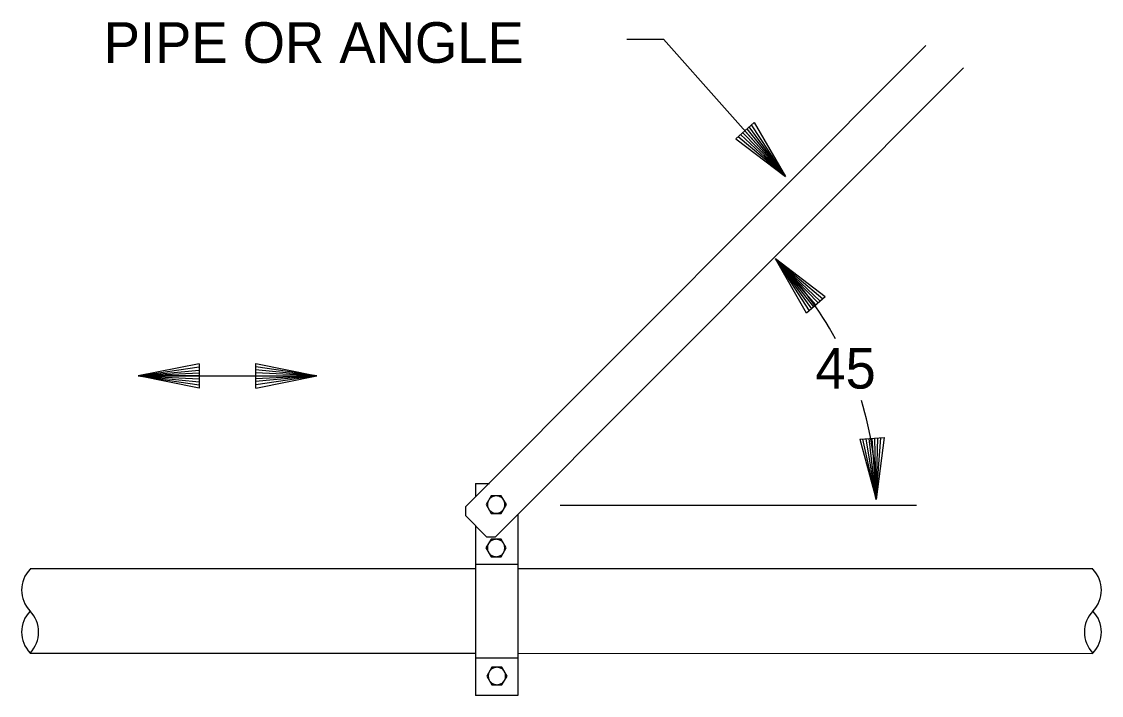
# Model space of a CAD drawing. Extents: x 10040.55 to 10045.84, y 10033.26 to 10035.76.
# Drawn here: x 10041.3056 to 10041.5711, y 10035.0779 to 10035.2436 of the extents above; entities that cross this region are included whole.
import ezdxf

# ---------------------------------------------------------------- set-up
doc = ezdxf.new("R2010")
doc.units = 0
doc.layers.add('Level 2', color=7, linetype='Continuous')

msp = doc.modelspace()

# ---------------------------------------------------------------- linework, layer by layer
at = {"layer": 'Level 2'}
for p, q in [((10041.414760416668, 10035.12428125), (10041.527947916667, 10035.237791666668)), ((10041.42215625, 10035.116947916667), (10041.537187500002, 10035.232312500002)), ((10041.481208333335, 10035.214812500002), (10041.485718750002, 10035.218802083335)), ((10041.483437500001, 10035.216802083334), (10041.493458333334, 10035.205552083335)), ((10041.493458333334, 10035.205552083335), (10041.484010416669, 10035.217291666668)), ((10041.493458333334, 10035.205552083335), (10041.484552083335, 10035.217791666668)), ((10041.493458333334, 10035.205552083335), (10041.485104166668, 10035.218270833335)), ((10041.485718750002, 10035.218802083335), (10041.493458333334, 10035.205552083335)), ((10041.481208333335, 10035.214812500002), (10041.493458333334, 10035.205552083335)), ((10041.493458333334, 10035.205552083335), (10041.48178125, 10035.215322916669)), ((10041.493458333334, 10035.205552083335), (10041.482395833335, 10035.215895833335)), ((10041.493458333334, 10035.205552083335), (10041.482916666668, 10035.216322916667)), ((10041.5009375, 10035.173968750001), (10041.490979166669, 10035.185270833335)), ((10041.498625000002, 10035.17196875), (10041.490979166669, 10035.185270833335)), ((10041.503166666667, 10035.175927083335), (10041.490979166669, 10035.185270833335)), ((10041.490979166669, 10035.185270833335), (10041.499812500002, 10035.172968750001)), ((10041.490979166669, 10035.185270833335), (10041.50196875, 10035.174854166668)), ((10041.490979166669, 10035.185270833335), (10041.499260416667, 10035.172510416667)), ((10041.490979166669, 10035.185270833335), (10041.500354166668, 10035.173468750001)), ((10041.490979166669, 10035.185270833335), (10041.501458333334, 10035.174437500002)), ((10041.490979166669, 10035.185270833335), (10041.502593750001, 10035.175427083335)), ((10041.503166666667, 10035.175927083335), (10041.498625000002, 10035.17196875)), ((10041.34928125, 10035.159500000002), (10041.334229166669, 10035.156500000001)), ((10041.334229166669, 10035.156500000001), (10041.34928125, 10035.158739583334)), ((10041.34928125, 10035.159500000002), (10041.349270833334, 10035.153479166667)), ((10041.363166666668, 10035.153500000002), (10041.363177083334, 10035.159520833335)), ((10041.378218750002, 10035.156500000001), (10041.363166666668, 10035.158708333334)), ((10041.363177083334, 10035.159520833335), (10041.378218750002, 10035.156500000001)), ((10041.334229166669, 10035.156500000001), (10041.349302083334, 10035.157895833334)), ((10041.334229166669, 10035.156500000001), (10041.34928125, 10035.15721875)), ((10041.349291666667, 10035.156520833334), (10041.334229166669, 10035.156500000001)), ((10041.334229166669, 10035.156500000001), (10041.378218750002, 10035.156500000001)), ((10041.349270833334, 10035.153479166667), (10041.334229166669, 10035.156500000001)), ((10041.334229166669, 10035.156500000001), (10041.349291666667, 10035.155020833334)), ((10041.334229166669, 10035.156500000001), (10041.34928125, 10035.154291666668)), ((10041.334229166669, 10035.156500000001), (10041.34928125, 10035.155760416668)), ((10041.378218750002, 10035.156500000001), (10041.363145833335, 10035.155104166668)), ((10041.378218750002, 10035.156500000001), (10041.363156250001, 10035.157979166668)), ((10041.363156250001, 10035.156479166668), (10041.378218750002, 10035.156500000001)), ((10041.378218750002, 10035.156500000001), (10041.363166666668, 10035.157239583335)), ((10041.363166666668, 10035.153500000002), (10041.378218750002, 10035.156500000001)), ((10041.378218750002, 10035.156500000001), (10041.363166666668, 10035.155781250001)), ((10041.378218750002, 10035.156500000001), (10041.363166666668, 10035.154260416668)), ((10041.511708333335, 10035.140895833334), (10041.517729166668, 10035.141322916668)), ((10041.511708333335, 10035.140895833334), (10041.515760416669, 10035.126093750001)), ((10041.515760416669, 10035.126093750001), (10041.512479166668, 10035.140958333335)), ((10041.515760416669, 10035.126093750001), (10041.513312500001, 10035.141031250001)), ((10041.515760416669, 10035.126093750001), (10041.513979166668, 10035.1410625)), ((10041.514687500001, 10035.141114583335), (10041.515760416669, 10035.126093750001)), ((10041.515760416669, 10035.126093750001), (10041.515437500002, 10035.141166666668)), ((10041.517729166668, 10035.141322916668), (10041.515760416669, 10035.126093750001)), ((10041.515760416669, 10035.126093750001), (10041.51690625, 10035.141260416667)), ((10041.515760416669, 10035.126093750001), (10041.516187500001, 10035.141229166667)), ((10041.41721875, 10035.130041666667), (10041.41721875, 10035.126750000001)), ((10041.41721875, 10035.130041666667), (10041.420656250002, 10035.130041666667)), ((10041.414760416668, 10035.124270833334), (10041.414760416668, 10035.122125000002)), ((10041.438000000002, 10035.124739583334), (10041.525697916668, 10035.124739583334)), ((10041.414760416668, 10035.122125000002), (10041.419958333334, 10035.116947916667)), ((10041.427635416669, 10035.122447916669), (10041.427635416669, 10035.07790625)), ((10041.41721875, 10035.119677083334), (10041.41721875, 10035.07790625)), ((10041.419958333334, 10035.116947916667), (10041.422166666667, 10035.116947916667)), ((10041.3076875, 10035.109093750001), (10041.41721875, 10035.109093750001)), ((10041.417229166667, 10035.110229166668), (10041.427666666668, 10035.110229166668)), ((10041.427635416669, 10035.109093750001), (10041.569041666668, 10035.109083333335)), ((10041.3076875, 10035.088260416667), (10041.41721875, 10035.088260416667)), ((10041.417229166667, 10035.087135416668), (10041.427666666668, 10035.087135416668)), ((10041.422322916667, 10035.087125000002), (10041.422322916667, 10035.087125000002)), ((10041.427635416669, 10035.088260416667), (10041.569041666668, 10035.08825)), ((10041.427635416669, 10035.07790625), (10041.41721875, 10035.07790625))]:
    msp.add_line(p, q, dxfattribs=at)
msp.add_lwpolyline([(10041.454468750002, 10035.239291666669), (10041.463468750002, 10035.239291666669), (10041.493458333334, 10035.205552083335)], dxfattribs=at)
for points in [[(10041.424812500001, 10035.124843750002), (10041.423562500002, 10035.127010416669), (10041.421062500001, 10035.127010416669), (10041.419812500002, 10035.124843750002), (10041.421062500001, 10035.122677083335), (10041.423562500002, 10035.122677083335)], [(10041.424458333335, 10035.124843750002), (10041.424447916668, 10035.124979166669), (10041.424437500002, 10035.125114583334), (10041.424416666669, 10035.125239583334), (10041.424385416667, 10035.125375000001), (10041.424354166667, 10035.125500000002), (10041.424302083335, 10035.125625), (10041.424250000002, 10035.125750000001), (10041.4241875, 10035.125875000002), (10041.424125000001, 10035.125989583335), (10041.424052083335, 10035.126104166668), (10041.423968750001, 10035.126208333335), (10041.423875, 10035.1263125), (10041.423781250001, 10035.126406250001), (10041.423677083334, 10035.126489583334), (10041.423572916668, 10035.126572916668), (10041.423458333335, 10035.126645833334), (10041.42334375, 10035.126718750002), (10041.423229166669, 10035.126781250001), (10041.423104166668, 10035.126833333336), (10041.422979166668, 10035.126875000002), (10041.42284375, 10035.126916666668), (10041.422718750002, 10035.126947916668), (10041.422583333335, 10035.12696875), (10041.422447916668, 10035.126979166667), (10041.4223125, 10035.126979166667), (10041.422177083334, 10035.126979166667), (10041.422041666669, 10035.12696875), (10041.421916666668, 10035.126947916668), (10041.421781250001, 10035.126916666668), (10041.42165625, 10035.126875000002), (10041.421531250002, 10035.126833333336), (10041.421406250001, 10035.126781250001), (10041.42128125, 10035.126718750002), (10041.421166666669, 10035.126645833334), (10041.421052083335, 10035.126572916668), (10041.420947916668, 10035.126489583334), (10041.420843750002, 10035.126406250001), (10041.420750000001, 10035.1263125), (10041.420666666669, 10035.126208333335), (10041.420583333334, 10035.126104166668), (10041.420510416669, 10035.125989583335), (10041.4204375, 10035.125875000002), (10041.420375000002, 10035.125750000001), (10041.420322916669, 10035.125625), (10041.42028125, 10035.125500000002), (10041.420239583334, 10035.125375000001), (10041.420208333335, 10035.125239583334), (10041.420187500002, 10035.125114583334), (10041.420177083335, 10035.124979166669), (10041.420177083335, 10035.124843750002), (10041.420177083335, 10035.124708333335), (10041.420187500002, 10035.124572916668), (10041.420208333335, 10035.1244375), (10041.420239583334, 10035.124312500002), (10041.42028125, 10035.124177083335), (10041.420322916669, 10035.124052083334), (10041.420375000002, 10035.123927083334), (10041.4204375, 10035.123812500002), (10041.420510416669, 10035.123697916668), (10041.420583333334, 10035.123583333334), (10041.420666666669, 10035.123479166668), (10041.420750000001, 10035.123375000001), (10041.420843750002, 10035.123281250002), (10041.420947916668, 10035.123187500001), (10041.421052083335, 10035.123104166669), (10041.421166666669, 10035.123031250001), (10041.42128125, 10035.122968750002), (10041.421406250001, 10035.12290625), (10041.421531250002, 10035.122854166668), (10041.42165625, 10035.122802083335), (10041.421781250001, 10035.122770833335), (10041.421916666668, 10035.122739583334), (10041.422041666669, 10035.12271875), (10041.422177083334, 10035.122708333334), (10041.4223125, 10035.122697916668), (10041.422447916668, 10035.122708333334), (10041.422583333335, 10035.12271875), (10041.422718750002, 10035.122739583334), (10041.42284375, 10035.122770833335), (10041.422979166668, 10035.122802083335), (10041.423104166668, 10035.122854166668), (10041.423229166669, 10035.12290625), (10041.42334375, 10035.122968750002), (10041.423458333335, 10035.123031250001), (10041.423572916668, 10035.123104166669), (10041.423677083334, 10035.123187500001), (10041.423781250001, 10035.123281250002), (10041.423875, 10035.123375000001), (10041.423968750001, 10035.123479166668), (10041.424052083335, 10035.123583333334), (10041.424125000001, 10035.123697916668), (10041.4241875, 10035.123812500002), (10041.424250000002, 10035.123927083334), (10041.424302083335, 10035.124052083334), (10041.424354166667, 10035.124177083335), (10041.424385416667, 10035.124312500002), (10041.424416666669, 10035.1244375), (10041.424437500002, 10035.124572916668)], [(10041.424781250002, 10035.114166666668), (10041.423541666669, 10035.116333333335), (10041.421031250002, 10035.116333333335), (10041.419791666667, 10035.114166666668), (10041.421031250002, 10035.112000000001), (10041.423541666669, 10035.112000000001)], [(10041.424427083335, 10035.114166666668), (10041.424427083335, 10035.114302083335), (10041.424406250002, 10035.114437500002), (10041.424385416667, 10035.114572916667), (10041.424364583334, 10035.114697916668), (10041.424322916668, 10035.114833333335), (10041.424281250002, 10035.114958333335), (10041.424229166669, 10035.115083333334), (10041.424166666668, 10035.115197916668), (10041.424093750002, 10035.115312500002), (10041.424020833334, 10035.115427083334), (10041.423937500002, 10035.115531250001), (10041.42384375, 10035.115635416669), (10041.423750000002, 10035.115729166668), (10041.423656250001, 10035.115812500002), (10041.423541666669, 10035.115895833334), (10041.423437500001, 10035.115979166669), (10041.423322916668, 10035.116041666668), (10041.423197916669, 10035.116104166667), (10041.423072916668, 10035.116156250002), (10041.422947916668, 10035.116208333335), (10041.422822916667, 10035.116239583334), (10041.4226875, 10035.116270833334), (10041.422552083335, 10035.116291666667), (10041.422416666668, 10035.116302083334), (10041.422291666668, 10035.116312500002), (10041.42215625, 10035.116302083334), (10041.422020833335, 10035.116291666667), (10041.421885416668, 10035.116270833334), (10041.421750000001, 10035.116239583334), (10041.421625, 10035.116208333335), (10041.421500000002, 10035.116156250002), (10041.421375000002, 10035.116104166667), (10041.421250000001, 10035.116041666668), (10041.421135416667, 10035.115979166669), (10041.421031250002, 10035.115895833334), (10041.420916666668, 10035.115812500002), (10041.420822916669, 10035.115729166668), (10041.420729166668, 10035.115635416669), (10041.420635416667, 10035.115531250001), (10041.420552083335, 10035.115427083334), (10041.420479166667, 10035.115312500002), (10041.420406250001, 10035.115197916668), (10041.420343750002, 10035.115083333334), (10041.420291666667, 10035.114958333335), (10041.420250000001, 10035.114833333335), (10041.420208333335, 10035.114697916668), (10041.420187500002, 10035.114572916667), (10041.420166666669, 10035.114437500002), (10041.420145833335, 10035.114302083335), (10041.420145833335, 10035.114166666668), (10041.420145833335, 10035.114031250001), (10041.420166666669, 10035.113895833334), (10041.420187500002, 10035.113760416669), (10041.420208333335, 10035.113635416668), (10041.420250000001, 10035.113500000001), (10041.420291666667, 10035.113375), (10041.420343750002, 10035.113250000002), (10041.420406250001, 10035.113135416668), (10041.420479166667, 10035.113020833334), (10041.420552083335, 10035.112906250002), (10041.420635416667, 10035.112802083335), (10041.420729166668, 10035.112697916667), (10041.420822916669, 10035.112604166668), (10041.420916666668, 10035.112520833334), (10041.421031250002, 10035.112437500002), (10041.421135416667, 10035.112354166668), (10041.421250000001, 10035.112291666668), (10041.421375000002, 10035.112229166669), (10041.421500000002, 10035.112177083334), (10041.421625, 10035.112125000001), (10041.421750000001, 10035.112093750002), (10041.421885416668, 10035.112062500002), (10041.422020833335, 10035.112041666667), (10041.42215625, 10035.11203125), (10041.422291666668, 10035.112020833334), (10041.422416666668, 10035.11203125), (10041.422552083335, 10035.112041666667), (10041.4226875, 10035.112062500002), (10041.422822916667, 10035.112093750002), (10041.422947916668, 10035.112125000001), (10041.423072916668, 10035.112177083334), (10041.423197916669, 10035.112229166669), (10041.423322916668, 10035.112291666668), (10041.423437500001, 10035.112354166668), (10041.423541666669, 10035.112437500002), (10041.423656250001, 10035.112520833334), (10041.423750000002, 10035.112604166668), (10041.42384375, 10035.112697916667), (10041.423937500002, 10035.112802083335), (10041.424020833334, 10035.112906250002), (10041.424093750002, 10035.113020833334), (10041.424166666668, 10035.113135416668), (10041.424229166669, 10035.113250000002), (10041.424281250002, 10035.113375), (10041.424322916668, 10035.113500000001), (10041.424364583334, 10035.113635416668), (10041.424385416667, 10035.113760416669), (10041.424406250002, 10035.113895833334)], [(10041.424979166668, 10035.082677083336), (10041.423729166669, 10035.08484375), (10041.421229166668, 10035.08484375), (10041.419979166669, 10035.082677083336), (10041.421229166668, 10035.080520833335), (10041.423729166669, 10035.080520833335)], [(10041.424625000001, 10035.082677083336), (10041.424625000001, 10035.0828125), (10041.424604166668, 10035.082947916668), (10041.424583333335, 10035.083083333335), (10041.424562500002, 10035.083218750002), (10041.424520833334, 10035.08334375), (10041.424479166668, 10035.083468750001), (10041.424427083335, 10035.083593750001), (10041.424364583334, 10035.083708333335), (10041.424291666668, 10035.083833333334), (10041.424218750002, 10035.083937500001), (10041.424135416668, 10035.084041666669), (10041.424041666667, 10035.084145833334), (10041.423947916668, 10035.084239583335), (10041.423854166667, 10035.084333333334), (10041.423739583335, 10035.084416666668), (10041.423635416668, 10035.084489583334), (10041.423520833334, 10035.084562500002), (10041.423395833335, 10035.084614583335), (10041.423270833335, 10035.084677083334), (10041.423145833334, 10035.084718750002), (10041.423020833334, 10035.084760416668), (10041.422885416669, 10035.084781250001), (10041.422750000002, 10035.084802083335), (10041.422614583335, 10035.084822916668), (10041.422479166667, 10035.084822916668), (10041.422354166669, 10035.084822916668), (10041.422218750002, 10035.084802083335), (10041.422083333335, 10035.084781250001), (10041.421947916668, 10035.084760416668), (10041.421822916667, 10035.084718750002), (10041.421697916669, 10035.084677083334), (10041.421572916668, 10035.084614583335), (10041.421447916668, 10035.084562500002), (10041.421333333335, 10035.084489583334), (10041.421229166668, 10035.084416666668), (10041.421114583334, 10035.084333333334), (10041.421020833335, 10035.084239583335), (10041.420927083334, 10035.084145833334), (10041.420833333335, 10035.084041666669), (10041.420750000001, 10035.083937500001), (10041.420677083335, 10035.083833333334), (10041.420604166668, 10035.083708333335), (10041.420541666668, 10035.083593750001), (10041.420489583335, 10035.083468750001), (10041.420447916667, 10035.08334375), (10041.420406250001, 10035.083218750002), (10041.420385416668, 10035.083083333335), (10041.420364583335, 10035.082947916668), (10041.420343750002, 10035.0828125), (10041.420343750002, 10035.082677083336), (10041.420343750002, 10035.082552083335), (10041.420364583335, 10035.082416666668), (10041.420385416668, 10035.082281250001), (10041.420406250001, 10035.082145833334), (10041.420447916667, 10035.082020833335), (10041.420489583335, 10035.081895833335), (10041.420541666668, 10035.081770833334), (10041.420604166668, 10035.081645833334), (10041.420677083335, 10035.081531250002), (10041.420750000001, 10035.081427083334), (10041.420833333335, 10035.0813125), (10041.420927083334, 10035.081218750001), (10041.421020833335, 10035.081125), (10041.421114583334, 10035.081031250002), (10041.421229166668, 10035.080947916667), (10041.421333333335, 10035.080875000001), (10041.421447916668, 10035.080802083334), (10041.421572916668, 10035.080739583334), (10041.421697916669, 10035.080687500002), (10041.421822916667, 10035.080645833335), (10041.421947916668, 10035.080604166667), (10041.422083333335, 10035.080572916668), (10041.422218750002, 10035.080552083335), (10041.422354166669, 10035.080541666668), (10041.422479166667, 10035.080541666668), (10041.422614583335, 10035.080541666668), (10041.422750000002, 10035.080552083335), (10041.422885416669, 10035.080572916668), (10041.423020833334, 10035.080604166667), (10041.423145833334, 10035.080645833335), (10041.423270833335, 10035.080687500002), (10041.423395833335, 10035.080739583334), (10041.423520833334, 10035.080802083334), (10041.423635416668, 10035.080875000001), (10041.423739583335, 10035.080947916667), (10041.423854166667, 10035.081031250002), (10041.423947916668, 10035.081125), (10041.424041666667, 10035.081218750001), (10041.424135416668, 10035.0813125), (10041.424218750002, 10035.081427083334), (10041.424291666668, 10035.081531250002), (10041.424364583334, 10035.081645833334), (10041.424427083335, 10035.081770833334), (10041.424479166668, 10035.081895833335), (10041.424520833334, 10035.082020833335), (10041.424562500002, 10035.082145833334), (10041.424583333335, 10035.082281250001), (10041.424604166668, 10035.082416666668)]]:
    msp.add_lwpolyline(points, close=True, dxfattribs=at)
for centre, radius, start, end in [((10041.43270616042, 10035.126098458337), 0.08305132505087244, 28.380758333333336, 45.43875), ((10041.43270616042, 10035.126098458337), 0.08305132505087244, 0, 17.029955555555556), ((10041.313026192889, 10035.1038131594), 0.007424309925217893, 135.97880833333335, 224.0225027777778), ((10041.563702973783, 10035.103802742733), 0.007424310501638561, 315.9774972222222, 44.021191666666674), ((10041.313026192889, 10035.093494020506), 0.007424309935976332, 135.97749722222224, 224.02119166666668), ((10041.302348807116, 10035.093494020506), 0.007424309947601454, 315.97880833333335, 44.02250277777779), ((10041.574380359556, 10035.09348360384), 0.007424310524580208, 135.97749722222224, 224.02119166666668), ((10041.563702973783, 10035.09348360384), 0.007424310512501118, 315.97880833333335, 44.02250277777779)]:
    msp.add_arc(centre, radius, start, end, dxfattribs=at)

# ---------------------------------------------------------------- texts
for s, p in [('PIPE OR ANGLE', (10041.325791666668, 10035.233500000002)), ('45', (10041.50078125, 10035.153375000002))]:
    msp.add_text(s, height=0.010000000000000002, dxfattribs=at).set_placement(p)

doc.saveas('drawing.dxf')
